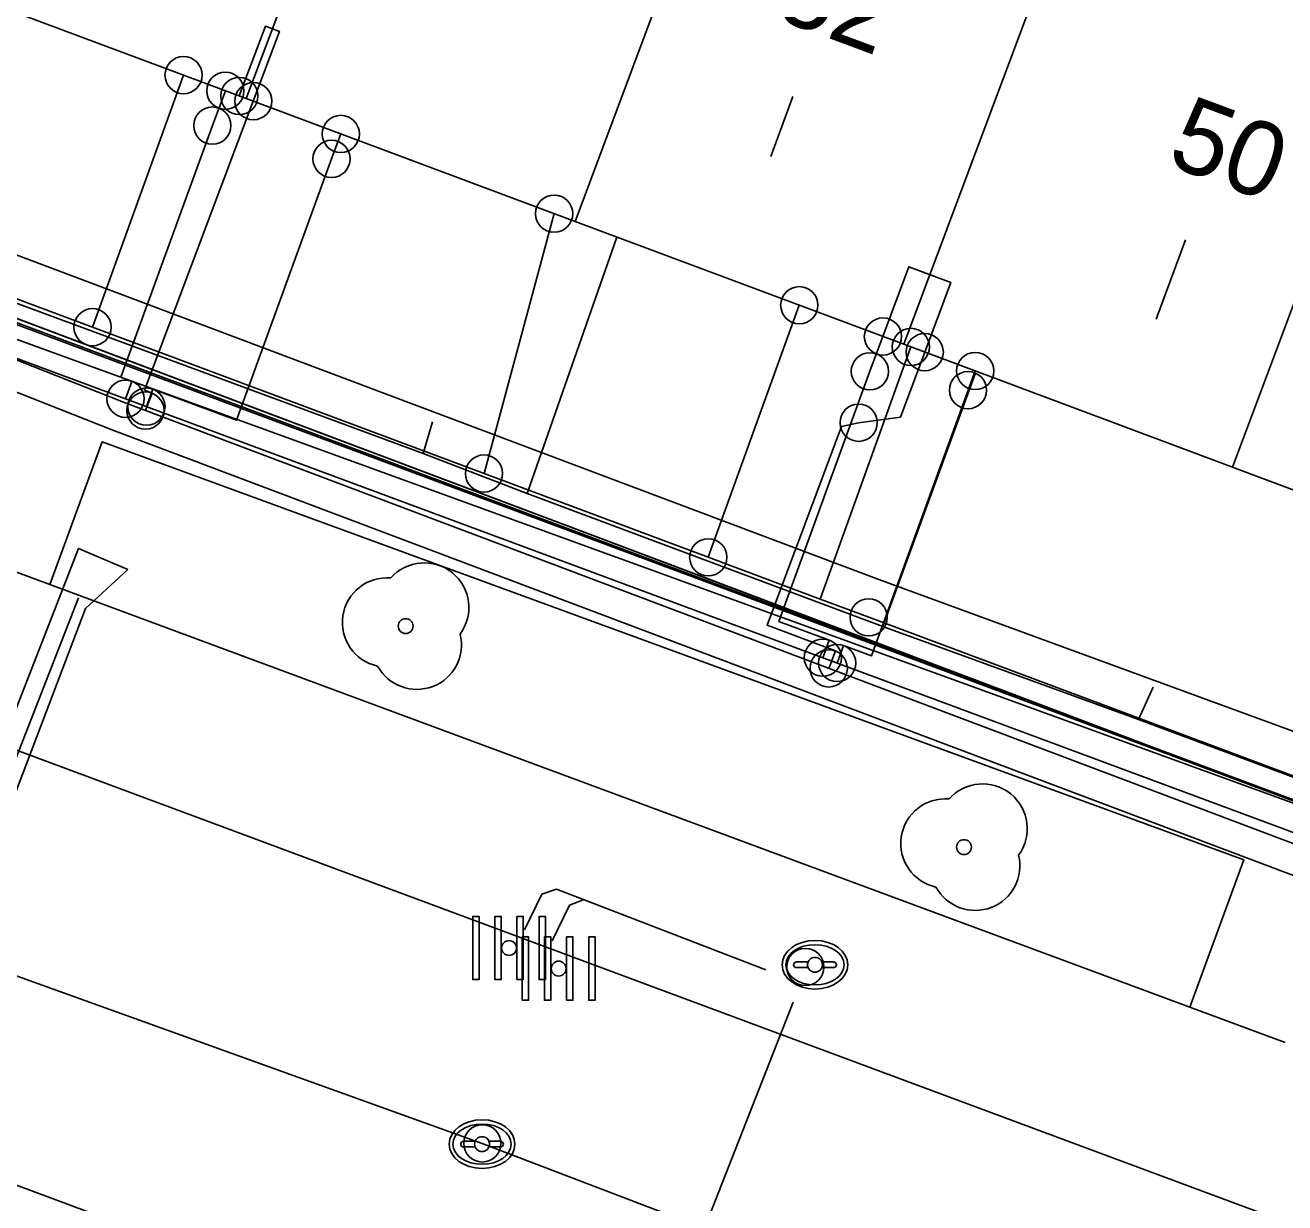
# Model space of a CAD drawing. Extents: x 192672 to 192910, y 446344 to 446512.
# Drawn here: x 192686.52 to 192703.44, y 446414.58 to 446430.41 of the extents above; entities that cross this region are included whole.
import ezdxf

# ---------------------------------------------------------------- set-up
doc = ezdxf.new("R2010")
doc.units = 0
for name, color, linetype in [('B-OI-KL-()_OVERIG_RIOOLVRIJVERVAL-S', 7, 'Continuous'), ('B-OI-KL-BUISLEIDING_OLIEGASCHEMICALIEN_GASLAGEDRUK-G', 7, 'Continuous'), ('B-OI-KL-DATA-G', 7, 'Continuous'), ('B-OI-KL-DATA_GTWP-S', 7, 'Continuous'), ('B-OI-KL-DATA_KABELBED-G', 7, 'Continuous'), ('B-OI-KL-DATA_MOF-S', 7, 'Continuous'), ('B-OI-KL-ET_LS-G', 7, 'Continuous'), ('B-OI-KL-ET_LS_DELIVERYPOINT-S', 7, 'Continuous'), ('B-OI-KL-ET_LS_MANTELBUIS-G', 7, 'Continuous'), ('B-OI-KL-ET_LS_MOF-S', 7, 'Continuous'), ('B-OI-KL-ET_MS-G', 7, 'Continuous'), ('B-OI-KL-GAS_LD_AFTAKZADEL-S', 7, 'Continuous'), ('B-OI-KL-GAS_LD_DELIVERYPOINT-S', 7, 'Continuous'), ('B-OI-KL-GAS_LD_OVERGANGSSTUK-S', 7, 'Continuous'), ('B-OI-KL-WATER-G', 7, 'Continuous'), ('B-OI-RI-RIOOLVRIJVERVAL-G', 7, 'Continuous'), ('boom', 7, 'Continuous'), ('Default', 7, 'Continuous'), ('huisnummerreeks BGT', 7, 'Continuous'), ('inspectie-   rioolput', 7, 'Continuous'), ('kant open verharding', 7, 'Continuous'), ('kant verharding', 7, 'Continuous'), ('kolk', 7, 'Continuous'), ('pand op maaiveld vlak', 7, 'Continuous'), ('verkeerseiland - berm', 7, 'Continuous')]:
    doc.layers.add(name, color=color, linetype=linetype)

# ---------------------------------------------------------------- blocks, each defined once
blk = doc.blocks.new('B-OI-KL-GAS_LD_AFTAKZADEL-S')
at = {"layer": 'Default'}
blk.add_circle((0, 0), 0.25, dxfattribs=at)
blk = doc.blocks.new('B-OI-KL-GAS_LD_DELIVERYPOINT-S')
at = {"layer": 'Default'}
blk.add_circle((0, 0), 0.25, dxfattribs=at)
blk = doc.blocks.new('B-OI-KL-GAS_LD_OVERGANGSSTUK-S')
at = {"layer": 'Default'}
blk.add_circle((0, 0), 0.25, dxfattribs=at)
blk = doc.blocks.new('B-OI-KL-ET_LS_DELIVERYPOINT-S')
at = {"layer": 'Default'}
blk.add_circle((0, 0), 0.25, dxfattribs=at)
blk = doc.blocks.new('B-OI-KL-ET_LS_MOF-S')
at = {"layer": 'Default'}
blk.add_circle((0, 0), 0.25, dxfattribs=at)
blk = doc.blocks.new('B-OI-KL-()_OVERIG_RIOOLVRIJVERVAL-S')
at = {"layer": 'Default'}
blk.add_circle((0, 0), 0.25, dxfattribs=at)
blk = doc.blocks.new('B-OI-KL-DATA_GTWP-S')
at = {"layer": 'Default'}
blk.add_circle((0, 0), 0.25, dxfattribs=at)
blk = doc.blocks.new('B-OI-KL-DATA_MOF-S')
at = {"layer": 'Default'}
blk.add_circle((0, 0), 0.25, dxfattribs=at)

msp = doc.modelspace()

# ---------------------------------------------------------------- linework, layer by layer
at = {"layer": 'B-OI-KL-BUISLEIDING_OLIEGASCHEMICALIEN_GASLAGEDRUK-G'}
for points in [[(192739.245, 446406.116), (192738.416, 446406.482), (192717.09, 446414.534), (192687.866, 446425.386), (192686.502, 446425.892), (192685.933, 446426.1), (192675.743, 446429.821)], [(192689.033, 446429.057), (192689.208, 446429.525)], [(192687.866, 446425.386), (192687.953, 446425.62), (192687.805, 446425.675), (192689.033, 446429.057)], [(192690.634, 446428.61), (192690.759, 446428.945)], [(192688.147, 446425.281), (192688.234, 446425.515), (192689.358, 446425.098), (192690.634, 446428.61)], [(192697.868, 446425.755), (192698.043, 446426.223)], [(192697.236, 446421.907), (192697.323, 446422.141), (192696.643, 446422.394), (192697.868, 446425.755)], [(192699.187, 446425.502), (192699.283, 446425.76)], [(192697.428, 446421.835), (192697.515, 446422.07), (192697.889, 446421.931), (192699.187, 446425.502)]]:
    msp.add_lwpolyline(points, dxfattribs=at)
at = {"layer": 'B-OI-KL-DATA-G'}
for points in [[(192768.74, 446486.807), (192749.794, 446435.599), (192742.072, 446415.039), (192739.06, 446406.841), (192720.2, 446413.77), (192719.012, 446414.118), (192696.077, 446422.823), (192683.193, 446427.673), (192678.122, 446429.261), (192675.743, 446430.156)], [(192675.743, 446430.36), (192720.2, 446413.771), (192739.906, 446406.53), (192752.421, 446411.058), (192770.152, 446404.44), (192773.577, 446403.064), (192825.629, 446383.71), (192826.856, 446388.539), (192834.171, 446407.983), (192839.017, 446421.742), (192838.042, 446426.7), (192842.865, 446440.095), (192846.683, 446450.008), (192848.26, 446453.903), (192848.365, 446454.374), (192848.254, 446454.945), (192844.011, 446462.681), (192860.643, 446470.952)], [(192745.236, 446436.264), (192745.276, 446436.371), (192749.491, 446434.791), (192742.072, 446415.039), (192739.06, 446406.841), (192720.2, 446413.77), (192719.012, 446414.118), (192696.077, 446422.823), (192683.193, 446427.673), (192678.122, 446429.261), (192675.743, 446430.156)], [(192737.667, 446407.73), (192737.22, 446407.782), (192736.663, 446407.985), (192736.03, 446408.286), (192735.626, 446408.365), (192729.863, 446410.472), (192728.465, 446411.08), (192721.146, 446413.773), (192716.247, 446415.615), (192710.715, 446417.628), (192706.774, 446419.101), (192701.477, 446421.077), (192698.04, 446422.325), (192693.262, 446424.115), (192691.867, 446424.65), (192684.239, 446427.468), (192680.591, 446428.834), (192677.798, 446429.859), (192675.743, 446430.624)], [(192675.743, 446430.156), (192678.122, 446429.261), (192683.193, 446427.673), (192696.077, 446422.823), (192719.012, 446414.118), (192720.2, 446413.77), (192739.06, 446406.841), (192738.917, 446406.249), (192738.75, 446405.758), (192738.438, 446405.088), (192738.002, 446404.406), (192737.543, 446403.858), (192737.067, 446403.408), (192736.56, 446403.025), (192736.06, 446402.723), (192733.684, 446396.245), (192734.518, 446394.712), (192730.316, 446383.423), (192727.316, 446375.697), (192722.899, 446364.033), (192722.458, 446362.715), (192718.077, 446351.086), (192716.68, 446347.404), (192715.968, 446345.556)], [(192675.743, 446430.156), (192678.122, 446429.261), (192683.193, 446427.673), (192696.077, 446422.823), (192719.012, 446414.118), (192720.2, 446413.77), (192739.06, 446406.841), (192738.917, 446406.249), (192738.75, 446405.758), (192738.438, 446405.088), (192738.002, 446404.406), (192737.543, 446403.858), (192737.067, 446403.408), (192736.56, 446403.025), (192736.06, 446402.723), (192733.684, 446396.245), (192734.518, 446394.712), (192730.316, 446383.423), (192727.316, 446375.697), (192722.899, 446364.033), (192722.458, 446362.715), (192718.077, 446351.086), (192716.68, 446347.404), (192715.968, 446345.556)], [(192675.743, 446430.156), (192678.122, 446429.261), (192683.193, 446427.673), (192696.077, 446422.823), (192719.012, 446414.118), (192720.2, 446413.77), (192739.06, 446406.841), (192738.917, 446406.249), (192738.75, 446405.758), (192738.438, 446405.088), (192738.002, 446404.406), (192737.543, 446403.858), (192737.067, 446403.408), (192736.56, 446403.025), (192736.06, 446402.723), (192733.684, 446396.245), (192734.518, 446394.712), (192730.316, 446383.423), (192727.316, 446375.697), (192722.899, 446364.033), (192722.458, 446362.715), (192718.077, 446351.086), (192716.68, 446347.404), (192715.968, 446345.556)], [(192675.743, 446430.156), (192678.122, 446429.261), (192683.193, 446427.673), (192696.077, 446422.823), (192719.012, 446414.118), (192720.2, 446413.77), (192739.06, 446406.841), (192738.917, 446406.249), (192738.75, 446405.758), (192738.438, 446405.088), (192738.002, 446404.406), (192737.543, 446403.858), (192737.067, 446403.408), (192736.56, 446403.025), (192736.06, 446402.723), (192733.684, 446396.245), (192734.518, 446394.712), (192730.316, 446383.423), (192727.316, 446375.697), (192722.899, 446364.033), (192722.458, 446362.715), (192718.077, 446351.086), (192716.68, 446347.404), (192715.968, 446345.556)], [(192675.743, 446430.156), (192678.122, 446429.261), (192683.193, 446427.673), (192696.077, 446422.823), (192719.012, 446414.118), (192720.2, 446413.77), (192739.06, 446406.841), (192738.917, 446406.249), (192738.75, 446405.758), (192738.438, 446405.088), (192738.002, 446404.406), (192737.543, 446403.858), (192737.067, 446403.408), (192736.56, 446403.025), (192736.06, 446402.723), (192733.684, 446396.245), (192734.518, 446394.712), (192730.316, 446383.423), (192727.316, 446375.697), (192722.899, 446364.033), (192722.458, 446362.715), (192718.077, 446351.086), (192716.68, 446347.404), (192715.968, 446345.556)], [(192675.743, 446430.156), (192678.122, 446429.261), (192683.193, 446427.673), (192696.077, 446422.823), (192719.012, 446414.118), (192720.2, 446413.77), (192739.06, 446406.841), (192738.917, 446406.249), (192738.75, 446405.758), (192738.438, 446405.088), (192738.002, 446404.406), (192737.543, 446403.858), (192737.067, 446403.408), (192736.56, 446403.025), (192736.06, 446402.723), (192733.684, 446396.245), (192734.518, 446394.712), (192730.316, 446383.423), (192727.316, 446375.697), (192722.899, 446364.033), (192722.458, 446362.715), (192718.077, 446351.086), (192716.68, 446347.404), (192715.968, 446345.556)], [(192696.833, 446429.449), (192696.537, 446428.642)], [(192693.262, 446424.115), (192694.468, 446427.559)], [(192691.867, 446424.65), (192684.239, 446427.468)], [(192702.107, 446427.52), (192701.716, 446426.456)], [(192698.04, 446422.325), (192699.284, 446425.723)], [(192691.867, 446424.65), (192691.993, 446425.078)], [(192693.262, 446424.115), (192691.867, 446424.65)], [(192698.04, 446422.325), (192693.262, 446424.115)], [(192701.477, 446421.077), (192698.04, 446422.325)], [(192715.968, 446345.556), (192716.68, 446347.404), (192718.077, 446351.086), (192722.458, 446362.715), (192722.899, 446364.033), (192727.316, 446375.697), (192730.316, 446383.423), (192734.518, 446394.712), (192733.684, 446396.245), (192736.06, 446402.723), (192736.56, 446403.025), (192737.067, 446403.408), (192737.543, 446403.858), (192738.002, 446404.406), (192738.438, 446405.088), (192738.75, 446405.758), (192738.917, 446406.249), (192739.06, 446406.841), (192720.2, 446413.77), (192719.012, 446414.118), (192698.154, 446422.035)], [(192701.477, 446421.077), (192701.676, 446421.509)], [(192706.774, 446419.101), (192701.477, 446421.077)], [(192715.968, 446345.556), (192716.68, 446347.404), (192718.077, 446351.086), (192722.458, 446362.715), (192722.899, 446364.033), (192727.316, 446375.697), (192730.316, 446383.423), (192734.518, 446394.712), (192733.684, 446396.245), (192736.06, 446402.723), (192736.56, 446403.025), (192737.067, 446403.408), (192737.543, 446403.858), (192738.002, 446404.406), (192738.438, 446405.088), (192738.75, 446405.758), (192738.917, 446406.249), (192739.06, 446406.841), (192720.2, 446413.77), (192719.012, 446414.118), (192703.056, 446420.174)]]:
    msp.add_lwpolyline(points, dxfattribs=at)
at = {"layer": 'B-OI-KL-DATA_KABELBED-G'}
for points in [[(192738.388, 446407.619), (192734.688, 446408.978), (192724.883, 446412.582), (192723.845, 446412.963), (192720.372, 446414.239), (192719.183, 446414.479), (192716.646, 446415.427), (192714.21, 446416.337), (192707.529, 446418.834), (192703.97, 446420.164), (192697.852, 446422.451), (192697.2, 446422.694), (192695.696, 446423.256), (192692.683, 446424.382), (192687.423, 446426.348), (192680.18, 446429.054), (192675.857, 446430.67), (192675.743, 446430.712)], [(192687.423, 446426.348), (192688.646, 446429.735)], [(192696.833, 446429.449), (192696.537, 446428.642)], [(192692.683, 446424.382), (192693.625, 446427.874)], [(192702.107, 446427.52), (192701.716, 446426.456)], [(192689.435, 446425.323), (192684.245, 446427.277)], [(192695.696, 446423.256), (192696.919, 446426.643)], [(192697.852, 446422.451), (192697.2, 446422.694), (192698.418, 446426.083)], [(192694.561, 446423.394), (192689.435, 446425.323)], [(192698.154, 446422.035), (192694.561, 446423.394)], [(192699.801, 446421.41), (192698.154, 446422.035)], [(192703.056, 446420.174), (192699.801, 446421.41)], [(192704.85, 446419.493), (192703.056, 446420.174)]]:
    msp.add_lwpolyline(points, dxfattribs=at)
at = {"layer": 'B-OI-KL-ET_LS-G'}
for points in [[(192689.583, 446429.385), (192689.933, 446430.322), (192689.745, 446430.392), (192689.395, 446429.455)], [(192675.743, 446430.115), (192687.837, 446425.34), (192737.952, 446406.43)], [(192751.683, 446410.693), (192751.552, 446410.731), (192751.472, 446410.738), (192751.395, 446410.716), (192751.332, 446410.668), (192751.29, 446410.599), (192748.269, 446402.545), (192740.519, 446405.455), (192737.866, 446406.039), (192687.696, 446424.966), (192675.743, 446429.685)], [(192688.134, 446425.228), (192688.222, 446425.462), (192688.119, 446425.501), (192689.583, 446429.385)], [(192698.605, 446426.013), (192698.955, 446426.95), (192698.393, 446427.16), (192698.043, 446426.223)], [(192697.717, 446425.064), (192698.278, 446425.137), (192698.605, 446426.013)], [(192697.315, 446421.763), (192697.404, 446421.997), (192696.487, 446422.344), (192697.485, 446425.014), (192697.717, 446425.064)], [(192687.898, 446423.091), (192687.234, 446423.375), (192682.544, 446411.341), (192675.743, 446413.827)], [(192705.001, 446404.897), (192704.48, 446404.329), (192704.196, 446403.239), (192682.97, 446411.104), (192687.329, 446422.57), (192687.898, 446423.091)]]:
    msp.add_lwpolyline(points, dxfattribs=at)
at = {"layer": 'B-OI-KL-ET_LS_MANTELBUIS-G'}
msp.add_lwpolyline([(192687.234, 446422.712), (192683.539, 446413.236)], dxfattribs=at)
at = {"layer": 'B-OI-KL-ET_MS-G'}
msp.add_lwpolyline([(192675.743, 446430.392), (192719.08, 446414.198), (192720.2, 446413.771), (192739.907, 446406.53), (192740.419, 446406.767), (192749.859, 446410.199), (192752.421, 446411.058), (192770.152, 446404.44), (192774.571, 446402.692), (192787.766, 446397.768), (192806.764, 446390.772), (192825.096, 446383.91)], dxfattribs=at)
at = {"layer": 'B-OI-KL-WATER-G'}
msp.add_line((192675.743, 446430.057), (192738.889, 446407.111), dxfattribs=at)
at = {"layer": 'B-OI-RI-RIOOLVRIJVERVAL-G'}
msp.add_line((192675.743, 446421.466), (192692.66, 446415.38), dxfattribs=at)
for points in [[(192696.468, 446417.714), (192693.655, 446418.797), (192693.46, 446418.729), (192693.226, 446418.251)], [(192693.832, 446418.583), (192693.598, 446418.104)], [(192694.029, 446418.657), (192693.832, 446418.583)], [(192696.836, 446417.278), (192694.422, 446411.124)], [(192692.66, 446415.38), (192716.55, 446406.25)]]:
    msp.add_lwpolyline(points, dxfattribs=at)
at = {"layer": 'boom'}
for centre in [(192691.63, 446422.331), (192699.133, 446419.361)]:
    msp.add_circle(centre, 0.1, dxfattribs=at)
for centre, radius, start, end in [((192691.88, 446422.581), 0.6, 323.5446, 138.4658), ((192691.38, 446422.381), 0.6, 85.137, 257.7544), ((192691.63, 446422.331), 0.1, 0, 180), ((192691.63, 446422.331), 0.1, 180, 0), ((192691.78, 446422.081), 0.6, 208.5058, 13.8356), ((192699.383, 446419.611), 0.6, 323.5446, 138.4658), ((192698.883, 446419.411), 0.6, 85.137, 257.7544), ((192699.133, 446419.361), 0.1, 0, 180), ((192699.133, 446419.361), 0.1, 180, 0), ((192699.283, 446419.111), 0.6, 208.5058, 13.8356)]:
    msp.add_arc(centre, radius, start, end, dxfattribs=at)
at = {"layer": 'inspectie-   rioolput'}
for p, q in [((192697.037, 446417.818), (192696.88, 446417.818)), ((192696.88, 446417.742), (192697.037, 446417.742)), ((192697.38, 446417.818), (192697.223, 446417.818)), ((192697.223, 446417.742), (192697.38, 446417.742)), ((192692.564, 446415.408), (192692.407, 446415.408)), ((192692.907, 446415.408), (192692.75, 446415.408)), ((192692.407, 446415.333), (192692.564, 446415.333)), ((192692.75, 446415.333), (192692.907, 446415.333))]:
    msp.add_line(p, q, dxfattribs=at)
for centre, radius, start, end in [((192696.88, 446417.78), 0.0375, 90, 270), ((192697.13, 446417.78), 0.1, 0, 180), ((192697.13, 446417.78), 0.1, 157.9757, 180), ((192697.13, 446417.78), 0.1, 180, 202.0243), ((192697.13, 446417.78), 0.1, 180, 0), ((192697.13, 446417.78), 0.1, 0, 22.0243), ((192697.13, 446417.78), 0.1, 337.9757, 0), ((192697.38, 446417.78), 0.0375, 270, 90), ((192692.407, 446415.37), 0.0375, 90, 270), ((192692.657, 446415.37), 0.1, 0, 180), ((192692.657, 446415.37), 0.1, 157.9757, 180), ((192692.657, 446415.37), 0.1, 180, 202.0243), ((192692.657, 446415.37), 0.1, 180, 0), ((192692.657, 446415.37), 0.1, 0, 22.0243), ((192692.657, 446415.37), 0.1, 337.9757, 0), ((192692.907, 446415.37), 0.0375, 270, 90)]:
    msp.add_arc(centre, radius, start, end, dxfattribs=at)
for centre, major_axis, ratio in [((192697.13, 446417.78), (-0.442, 0), 0.73911), ((192697.13, 446417.78), (-0.392, 0), 0.689655), ((192692.657, 446415.37), (-0.442, 0), 0.73911), ((192692.657, 446415.37), (-0.392, 0), 0.689655)]:
    msp.add_ellipse(centre, major_axis=major_axis, ratio=ratio, dxfattribs=at)
at = {"layer": 'kant open verharding'}
msp.add_lwpolyline([(192675.743, 446431.332), (192697.987, 446422.959), (192719.324, 446415.141), (192720.614, 446414.897)], dxfattribs=at)
at = {"layer": 'kant verharding'}
for p, q in [((192675.743, 446424.623), (192733.082, 446403.313)), ((192686.85, 446422.89), (192685.668, 446423.329)), ((192675.743, 446418.762), (192731.114, 446398.266)), ((192703.446, 446416.734), (192702.166, 446417.209))]:
    msp.add_line(p, q, dxfattribs=at)
at = {"layer": 'kolk'}
for points in [[(192692.616, 446418.006), (192692.616, 446418.431), (192692.531, 446418.431), (192692.531, 446418.006), (192692.531, 446417.581), (192692.616, 446417.581)], [(192692.914, 446418.006), (192692.914, 446418.431), (192692.829, 446418.431), (192692.829, 446418.006), (192692.829, 446417.581), (192692.914, 446417.581)], [(192693.211, 446418.006), (192693.211, 446418.431), (192693.126, 446418.431), (192693.126, 446418.006), (192693.126, 446417.581), (192693.211, 446417.581)], [(192693.509, 446418.006), (192693.509, 446418.431), (192693.424, 446418.431), (192693.424, 446418.006), (192693.424, 446417.581), (192693.509, 446417.581)], [(192693.282, 446417.729), (192693.282, 446418.154), (192693.197, 446418.154), (192693.197, 446417.729), (192693.197, 446417.304), (192693.282, 446417.304)], [(192693.58, 446417.729), (192693.58, 446418.154), (192693.495, 446418.154), (192693.495, 446417.729), (192693.495, 446417.304), (192693.58, 446417.304)], [(192693.877, 446417.729), (192693.877, 446418.154), (192693.792, 446418.154), (192693.792, 446417.729), (192693.792, 446417.304), (192693.877, 446417.304)], [(192694.175, 446417.729), (192694.175, 446418.154), (192694.09, 446418.154), (192694.09, 446417.729), (192694.09, 446417.304), (192694.175, 446417.304)]]:
    msp.add_lwpolyline(points, close=True, dxfattribs=at)
for centre, start, end in [((192693.02, 446418.006), 0, 180), ((192693.02, 446418.006), 180, 0), ((192693.686, 446417.729), 0, 180), ((192693.686, 446417.729), 180, 0)]:
    msp.add_arc(centre, 0.1, start, end, dxfattribs=at)
at = {"layer": 'pand op maaiveld vlak'}
for p, q in [((192693.675, 446440.623), (192689.489, 446429.42)), ((192698.093, 446438.972), (192693.906, 446427.769)), ((192698.324, 446426.118), (192702.51, 446437.321)), ((192702.742, 446424.467), (192706.928, 446435.671)), ((192685.071, 446431.07), (192689.489, 446429.42)), ((192689.489, 446429.42), (192693.906, 446427.769)), ((192693.906, 446427.769), (192698.324, 446426.118)), ((192698.324, 446426.118), (192702.742, 446424.467)), ((192707.159, 446422.816), (192702.742, 446424.467))]:
    msp.add_line(p, q, dxfattribs=at)
at = {"layer": 'verkeerseiland - berm'}
msp.add_line((192702.166, 446417.209), (192686.85, 446422.89), dxfattribs=at)
msp.add_lwpolyline([(192702.166, 446417.209), (192702.891, 446419.191), (192687.553, 446424.809), (192686.85, 446422.89)], dxfattribs=at)

# ---------------------------------------------------------------- block references
at = {"layer": 'B-OI-KL-()_OVERIG_RIOOLVRIJVERVAL-S'}
for p in [(192697, 446417.75), (192692.66, 446415.38)]:
    msp.add_blockref('B-OI-KL-()_OVERIG_RIOOLVRIJVERVAL-S', p, dxfattribs=at)
at = {"layer": 'B-OI-KL-DATA_GTWP-S'}
for p in [(192688.646, 446429.735), (192693.625, 446427.874), (192696.919, 446426.643), (192687.423, 446426.348), (192698.418, 446426.083), (192692.683, 446424.382), (192695.696, 446423.256), (192697.852, 446422.45)]:
    msp.add_blockref('B-OI-KL-DATA_GTWP-S', p, dxfattribs=at)
at = {"layer": 'B-OI-KL-DATA_MOF-S'}
for p in [(192687.423, 446426.348), (192692.683, 446424.382), (192695.696, 446423.256), (192697.852, 446422.45)]:
    msp.add_blockref('B-OI-KL-DATA_MOF-S', p, dxfattribs=at)
at = {"layer": 'B-OI-KL-ET_LS_DELIVERYPOINT-S'}
for p in [(192689.395, 446429.455), (192689.583, 446429.385), (192698.043, 446426.223), (192698.605, 446426.013)]:
    msp.add_blockref('B-OI-KL-ET_LS_DELIVERYPOINT-S', p, dxfattribs=at)
at = {"layer": 'B-OI-KL-ET_LS_MOF-S'}
for p in [(192688.134, 446425.228), (192697.717, 446425.064), (192697.315, 446421.763)]:
    msp.add_blockref('B-OI-KL-ET_LS_MOF-S', p, dxfattribs=at)
at = {"layer": 'B-OI-KL-GAS_LD_AFTAKZADEL-S'}
for p in [(192687.866, 446425.386), (192688.147, 446425.281), (192697.236, 446421.907), (192697.428, 446421.835)]:
    msp.add_blockref('B-OI-KL-GAS_LD_AFTAKZADEL-S', p, dxfattribs=at)
at = {"layer": 'B-OI-KL-GAS_LD_DELIVERYPOINT-S'}
for p in [(192689.208, 446429.525), (192690.759, 446428.945), (192698.043, 446426.223), (192699.283, 446425.76)]:
    msp.add_blockref('B-OI-KL-GAS_LD_DELIVERYPOINT-S', p, dxfattribs=at)
at = {"layer": 'B-OI-KL-GAS_LD_OVERGANGSSTUK-S'}
for p in [(192689.033, 446429.057), (192690.634, 446428.61), (192697.868, 446425.755), (192699.187, 446425.502)]:
    msp.add_blockref('B-OI-KL-GAS_LD_OVERGANGSSTUK-S', p, dxfattribs=at)

# ---------------------------------------------------------------- texts
at = {"layer": 'huisnummerreeks BGT'}
for s, p in [('52', (192696.568, 446430.51)), ('50', (192701.832, 446428.543))]:
    msp.add_text(s, height=1, rotation=339.6, dxfattribs=at).set_placement(p)

doc.saveas('drawing.dxf')
